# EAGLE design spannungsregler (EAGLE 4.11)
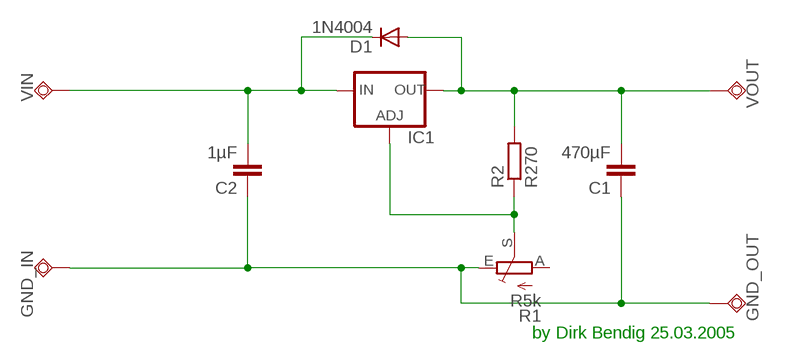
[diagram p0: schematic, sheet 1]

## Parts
C1  470µF  C-EU050-050X075  [C050-050X075]
C2  1µF  C-EU025-050X050  [C025-050X050]
D1  1N4004  [DO41-10]
GND_IN  TPSQPAD1-20  [P1-20]
GND_OUT  TPSQPAD1-20  [P1-20]
IC1  LM317TL  [317TL]
R1  R5k  TRIM_EU-LI10  [LI10]
R2  R270  R-EU_0207/10  [0207/10]
VIN  TPSQPAD1-20  [P1-20]
VOUT  TPSQPAD1-20  [P1-20]

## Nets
N$1: C2.2 D1.C IC1.3(IN) VIN.1(TP)
N$2: C1.1 C2.1 GND_IN.1(TP) GND_OUT.1(TP) R1.E
N$3: IC1.1(ADJ) R1.S R2.1
N$4: C1.2 D1.A IC1.2(OUT) R2.2 VOUT.1(TP)
Unconnected: R1.A

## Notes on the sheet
- by Dirk Bendig 25.03.2005

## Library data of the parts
C1 C2 = rcl:C-EU: CAPACITOR, European symbol
D1 = diode:1N4004: DIODE
GND_IN GND_OUT VIN VOUT = testpad:TPSQ
IC1 = v-reg:LM317TL: VOLTAGE REGULATOR
R1 = pot:TRIM_EU-: POTENTIOMETER
R2 = rcl:R-EU_: RESISTOR, European symbol

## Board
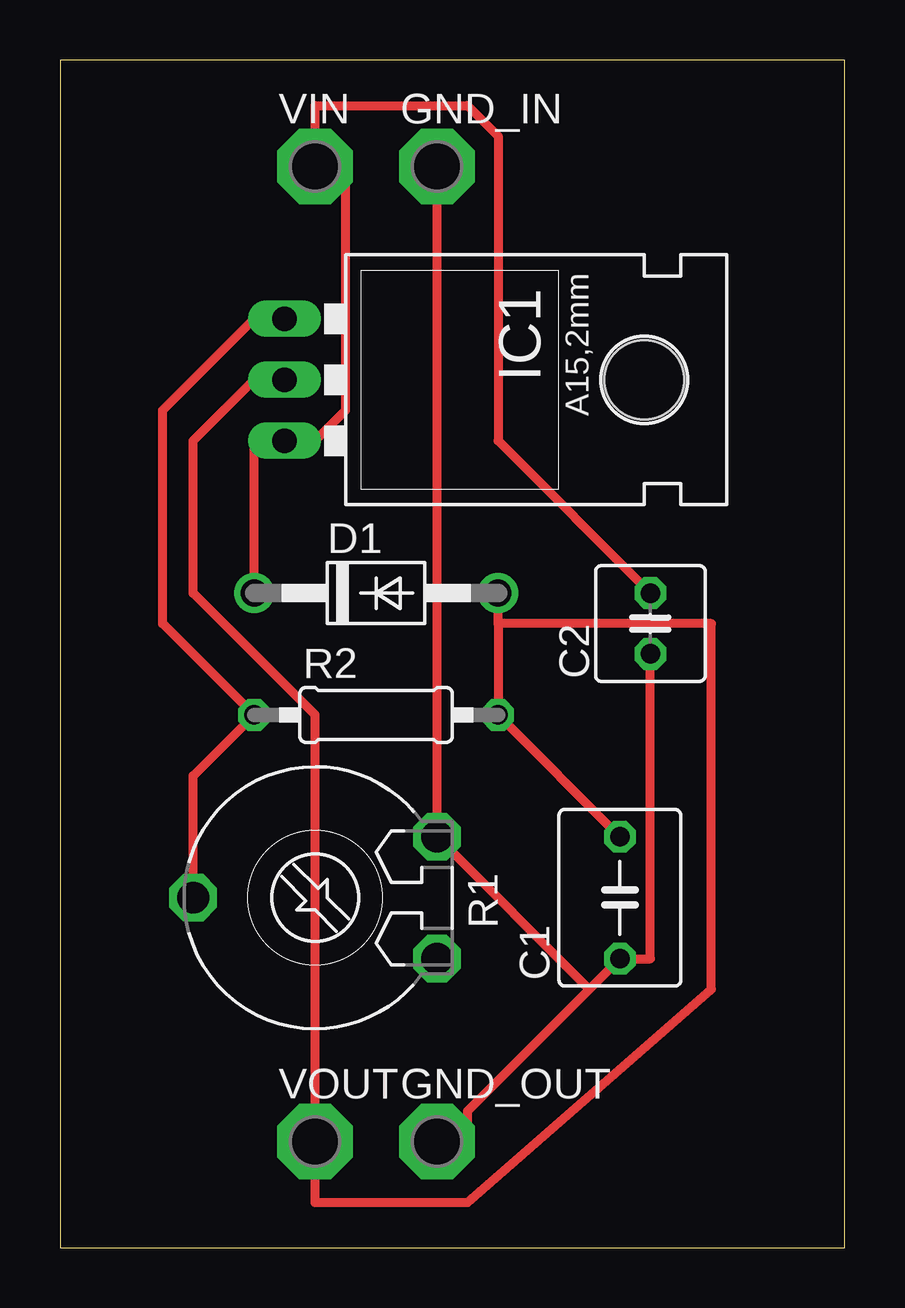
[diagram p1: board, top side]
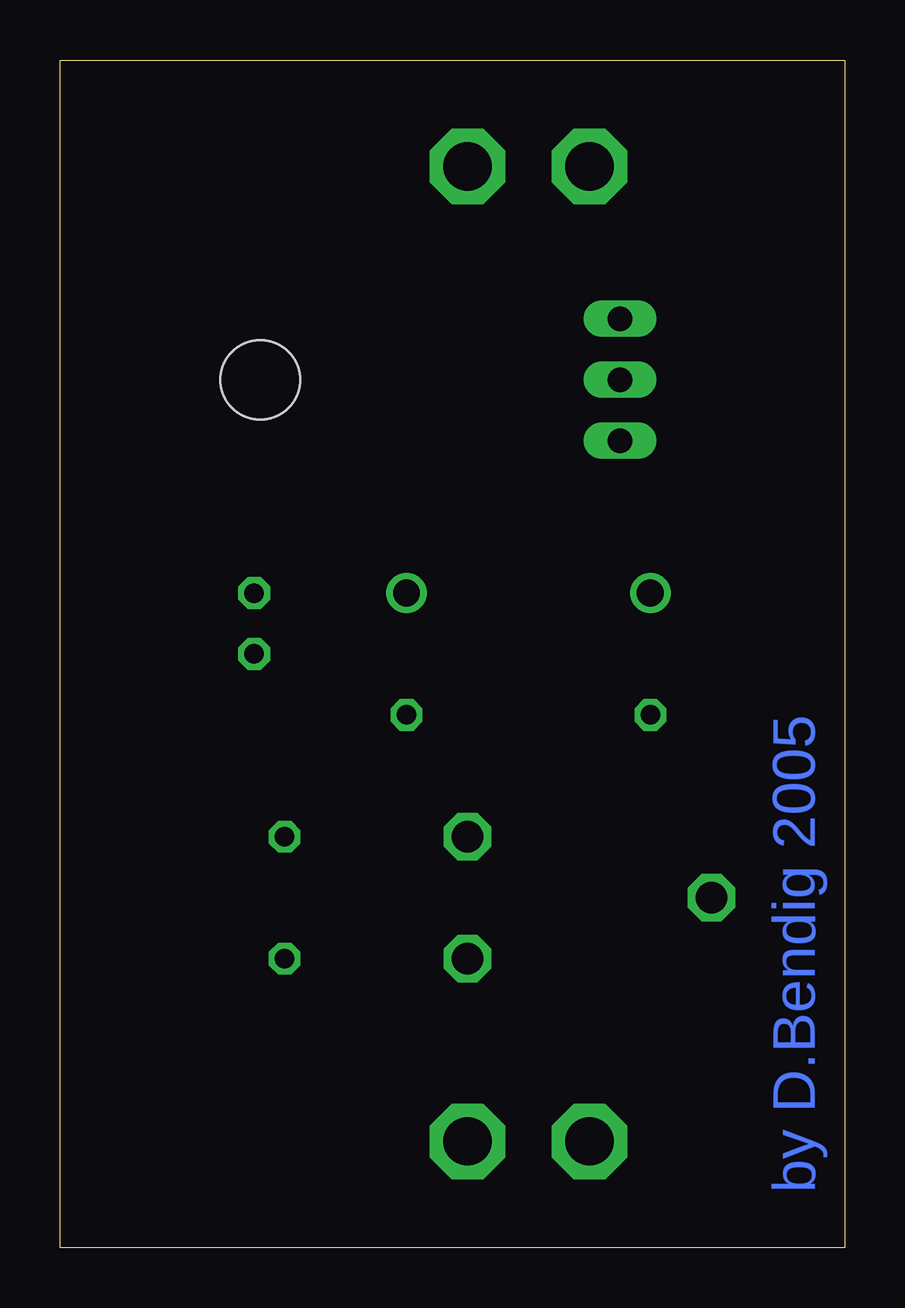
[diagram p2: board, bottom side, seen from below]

Size 32.69 x 49.52 mm. Coordinates in mm from the lower left corner, seen from the top.
Outline: 0,0 32.69,0 32.69,49.52 0,49.52 0,0
Copper layers (1*16): Top 0.035mm / dielectric 1.5mm / Bottom 0.035mm
Design rules "default": minimum track width 12mil, minimum drill 24mil, track to track 12mil, track to pad 12mil, pad to pad 12mil, via to via 12mil, smd to smd 8mil, copper to edge 40mil, drill to drill 8mil, minimum pad ring 10mil, minimum via ring 8mil, stop-mask expansion 4mil, vias tented up to drill 0mil, thermal gap 10mil

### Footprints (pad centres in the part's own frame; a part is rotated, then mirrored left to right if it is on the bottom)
C050-050X075 = drill 0.813 octagon: 1 -2.54,0; 2 2.54,0
C025-050X050 = drill 0.813 octagon: 1 -1.27,0; 2 1.27,0
DO41-10 = drill 1.118 round: A 5.08,0; C -5.08,0
P1-20 = drill 2.007 pad 3.15 octagon: 1 0,0
317TL = drill 1.016 long: 1 -2.54,-3.81; 2 0,-3.81; 3 2.54,-3.81 | hole 3.302: 0,11.176
LI10 = drill 1.321 octagon: A -2.54,-5.08; E 2.54,-5.08; S 0,5.08
0207/10 = drill 0.813 octagon: 1 -5.08,0; 2 5.08,0

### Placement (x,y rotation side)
C1  23.33,14.6 90 top
C2  24.6,26.03 90 top
D1  13.17,27.3 0 top
GND_IN  15.71,45.08 0 top
GND_OUT  15.71,4.44 0 top
IC1  13.17,36.19 270 top
R1  10.63,14.6 90 top
R2  13.17,22.22 0 top
VIN  10.63,45.08 0 top
VOUT  10.63,4.44 0 top

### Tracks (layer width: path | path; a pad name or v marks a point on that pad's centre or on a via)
N$1
  Top 0.381: D1.C 8.09,33.65 IC1.3 10.63,33.65 11.9,34.92 11.9,45.08 VIN.1 10.63,47.62 16.98,47.62 18.25,46.35 18.25,33.65 C2.2
N$2
  Top 0.381: 22.06,10.79 16.98,5.71 16.98,4.44 GND_OUT.1 | 22.06,10.79 C1.1 24.6,12.06 C2.1 | 22.06,10.79 R1.E GND_IN.1
N$3
  Top 0.381: R1.S 5.55,19.68 R2.1 4.28,26.03 4.28,34.92 8.09,38.73 IC1.1
N$4
  Top 0.381: 18.25,26.03 D1.A | 18.25,26.03 R2.2 C1.2 | IC1.2 8.09,36.19 5.55,33.65 5.55,27.3 10.63,22.22 VOUT.1 10.63,1.9 16.98,1.9 27.14,10.79 27.14,26.03 18.25,26.03

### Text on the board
Bottom: by D.Bendig 2005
